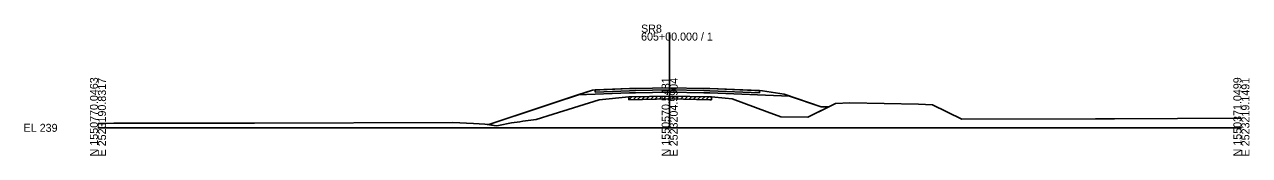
# Model space of a CAD drawing. Extents: x -26 to 2803, y -10 to 19537.
# Drawn here: x -25.7 to 402.8, y 11990.3 to 12036.2 of the extents above; entities that cross this region are included whole.
import ezdxf

# ---------------------------------------------------------------- set-up
doc = ezdxf.new("R2010")
doc.units = 0
for name, color, linetype in [('1', 7, 'Continuous'), ('Draft_XS_Grid', 7, 'Continuous'), ('Draft_XS_Text', 7, 'Continuous'), ('DTM_P_SUBGRADE_1', 7, 'Continuous'), ('DTM_X_GROUND', 7, 'Continuous'), ('SLOPE_STAKES_FILL', 7, 'Continuous'), ('XS_P_ASPHALT', 7, 'Continuous'), ('XS_P_SHOULDER', 7, 'Continuous')]:
    doc.layers.add(name, color=color, linetype=linetype)

msp = doc.modelspace()

# ---------------------------------------------------------------- linework, layer by layer
at = {"layer": '1'}
for p, q in [((200, 12000), (200, 12033.34)), ((0, 12000), (200, 12000)), ((200, 12000), (400, 12000))]:
    msp.add_line(p, q, dxfattribs=at)
at = {"layer": 'Draft_XS_Grid'}
for p, q in [((185.77, 12009.8), (186.79, 12010.82)), ((185.77, 12009.8), (185.77, 12010.8)), ((185.77, 12009.8), (200.14, 12010.11)), ((187.27, 12009.83), (188.29, 12010.85)), ((188.77, 12009.86), (189.79, 12010.88)), ((190.27, 12009.9), (191.29, 12010.92)), ((191.77, 12009.93), (192.79, 12010.95)), ((193.27, 12009.96), (194.29, 12010.98)), ((194.77, 12009.99), (195.79, 12011.02)), ((196.27, 12010.03), (197.29, 12011.05)), ((197.77, 12010.06), (198.79, 12011.08)), ((199.27, 12010.09), (200.29, 12011.11)), ((200.14, 12010.11), (214.06, 12009.83)), ((200.77, 12010.1), (201.75, 12011.08)), ((202.27, 12010.07), (203.25, 12011.05)), ((203.77, 12010.04), (204.75, 12011.02)), ((205.27, 12010.01), (206.25, 12010.99)), ((206.77, 12009.98), (207.75, 12010.96)), ((208.27, 12009.95), (209.25, 12010.93)), ((209.77, 12009.92), (210.75, 12010.9)), ((211.27, 12009.89), (212.25, 12010.87)), ((212.77, 12009.86), (213.75, 12010.84)), ((214.06, 12009.83), (214.59, 12009.82)), ((214.59, 12010.82), (214.59, 12009.82))]:
    msp.add_line(p, q, dxfattribs=at)
at = {"layer": 'Draft_XS_Text'}
for p, q in [((248.29, 12003.7), (258, 12008.55)), ((258, 12008.55), (263, 12008.75)), ((263, 12008.75), (275, 12008.51)), ((275, 12008.51), (287, 12008.27)), ((287, 12008.27), (292, 12008.07)), ((292, 12008.07), (302.19, 12002.98))]:
    msp.add_line(p, q, dxfattribs=at)
for points in [[(0.02, 12001.57), (2.38, 12001.57), (5.53, 12001.58), (44.07, 12001.62), (45.33, 12001.63), (48.48, 12001.63), (49.05, 12001.63), (54.75, 12001.65), (124.19, 12001.83), (131.36, 12001.5), (135.3, 12001.33), (139.27, 12000.74), (140.08, 12000.79), (144.66, 12001.73), (147.56, 12002.14), (148.66, 12002.3), (153.33, 12002.96), (159.28, 12004.79), (175.34, 12009.75), (185.77, 12010.8), (200.14, 12011.11), (214.06, 12010.83), (214.59, 12010.82), (219.37, 12010.41), (221.92, 12010.2), (234.11, 12005.62), (238.87, 12003.83), (248.29, 12003.7)], [(302.19, 12002.98), (349.02, 12003.11), (350.7, 12003.11), (351.94, 12003.11), (352.35, 12003.12), (353.16, 12003.12), (355.62, 12003.13), (399.74, 12003.37)]]:
    msp.add_lwpolyline(points, dxfattribs=at)
at = {"layer": 'DTM_P_SUBGRADE_1'}
for p, q in [((186, 12012.23), (167.87, 12011.5)), ((188, 12012.27), (186, 12012.23)), ((188, 12012.27), (200, 12012.51)), ((200, 12012.51), (212, 12012.27)), ((212, 12012.27), (214, 12012.23)), ((214, 12012.23), (241.87, 12011.11))]:
    msp.add_line(p, q, dxfattribs=at)
at = {"layer": 'DTM_X_GROUND'}
for p, q in [((172.99, 12013.21), (136.71, 12001.12)), ((186, 12013.73), (172.99, 12013.21)), ((188, 12013.77), (186, 12013.73)), ((188, 12013.77), (200, 12014.01)), ((200, 12014.01), (212, 12013.77)), ((212, 12013.77), (214, 12013.73)), ((214, 12013.73), (232.44, 12012.99)), ((232.44, 12012.99), (240.02, 12011.73)), ((240.02, 12011.73), (253.04, 12007.4)), ((253.04, 12007.4), (255.69, 12007.4))]:
    msp.add_line(p, q, dxfattribs=at)
at = {"layer": 'SLOPE_STAKES_FILL'}
for p, q in [((136.71, 12001.12), (172.99, 12013.21)), ((172.99, 12013.21), (186, 12013.73)), ((186, 12013.73), (188, 12013.77)), ((188, 12013.77), (200, 12014.01)), ((200, 12014.01), (212, 12013.77)), ((212, 12013.77), (214, 12013.73)), ((214, 12013.73), (232.44, 12012.99)), ((232.44, 12012.99), (240.02, 12011.73)), ((240.02, 12011.73), (253.04, 12007.4)), ((255.69, 12007.4), (258, 12008.55)), ((258, 12008.55), (263, 12008.75)), ((263, 12008.75), (275, 12008.51)), ((275, 12008.51), (287, 12008.27)), ((287, 12008.27), (292, 12008.07)), ((292, 12008.07), (302.19, 12002.98)), ((253.04, 12007.4), (255.69, 12007.4))]:
    msp.add_line(p, q, dxfattribs=at)
for points in [[(302.19, 12002.98), (349.02, 12003.11), (350.7, 12003.11), (351.94, 12003.11), (352.35, 12003.12), (353.16, 12003.12), (355.62, 12003.13), (399.74, 12003.37)], [(0.02, 12001.57), (2.38, 12001.57), (5.53, 12001.58), (44.07, 12001.62), (45.33, 12001.63), (48.48, 12001.63), (49.05, 12001.63), (54.75, 12001.65), (124.19, 12001.83), (131.36, 12001.5), (135.3, 12001.33), (136.71, 12001.12)]]:
    msp.add_lwpolyline(points, dxfattribs=at)
at = {"layer": 'XS_P_ASPHALT'}
for p, q in [((173.99, 12012.5), (173.99, 12013.25)), ((186, 12012.98), (173.99, 12012.5)), ((188, 12013.02), (186, 12012.98)), ((188, 12013.02), (200, 12013.26)), ((200, 12013.26), (212, 12013.02)), ((212, 12013.02), (214, 12012.98)), ((214, 12012.98), (231.41, 12012.28)), ((231.41, 12012.28), (231.41, 12013.03))]:
    msp.add_line(p, q, dxfattribs=at)
at = {"layer": 'XS_P_SHOULDER'}
for points in [[(186, 12012.23), (167.87, 12011.5), (136.71, 12001.12), (139.27, 12000.74), (140.08, 12000.79), (144.66, 12001.73), (147.56, 12002.14), (148.66, 12002.3), (153.33, 12002.96), (159.28, 12004.79), (175.34, 12009.75), (185.77, 12010.8), (200.14, 12011.11), (214.06, 12010.83), (214.59, 12010.82), (219.37, 12010.41), (221.92, 12010.2), (234.11, 12005.62), (238.87, 12003.83), (248.29, 12003.7), (255.69, 12007.4), (253.04, 12007.4), (241.87, 12011.11), (214, 12012.23), (212, 12012.27), (200, 12012.51), (188, 12012.27)], [(186, 12012.23), (167.87, 12011.5), (172.99, 12013.21), (173.99, 12013.25), (173.99, 12012.5), (186, 12012.98), (188, 12013.02), (200, 12013.26), (212, 12013.02), (214, 12012.98), (231.41, 12012.28), (231.41, 12013.03), (232.44, 12012.99), (240.02, 12011.73), (241.87, 12011.11), (214, 12012.23), (212, 12012.27), (200, 12012.51), (188, 12012.27)], [(186, 12012.98), (173.99, 12012.5), (173.99, 12013.25), (186, 12013.73), (188, 12013.77), (200, 12014.01), (212, 12013.77), (214, 12013.73), (231.41, 12013.03), (231.41, 12012.28), (214, 12012.98), (212, 12013.02), (200, 12013.26), (188, 12013.02)]]:
    msp.add_lwpolyline(points, close=True, dxfattribs=at)

# ---------------------------------------------------------------- texts
at = {"layer": '1'}
for s, p in [('SR8', (190, 12033.34)), ('605+00.000 / 1', (190, 12030.54)), ('EL 239', (-26, 11998.6))]:
    msp.add_text(s, height=2.8, dxfattribs=at).set_placement(p)
for s, p in [('N 1550770.0463', (0, 11990)), ('E 2523190.8317', (2.8, 11990)), ('N 1550570.5481', (200, 11990)), ('E 2523204.9904', (202.8, 11990)), ('N 1550371.0499', (400, 11990)), ('E 2523219.1491', (402.8, 11990))]:
    msp.add_text(s, height=2.8, rotation=90, dxfattribs=at).set_placement(p)

doc.saveas('drawing.dxf')
